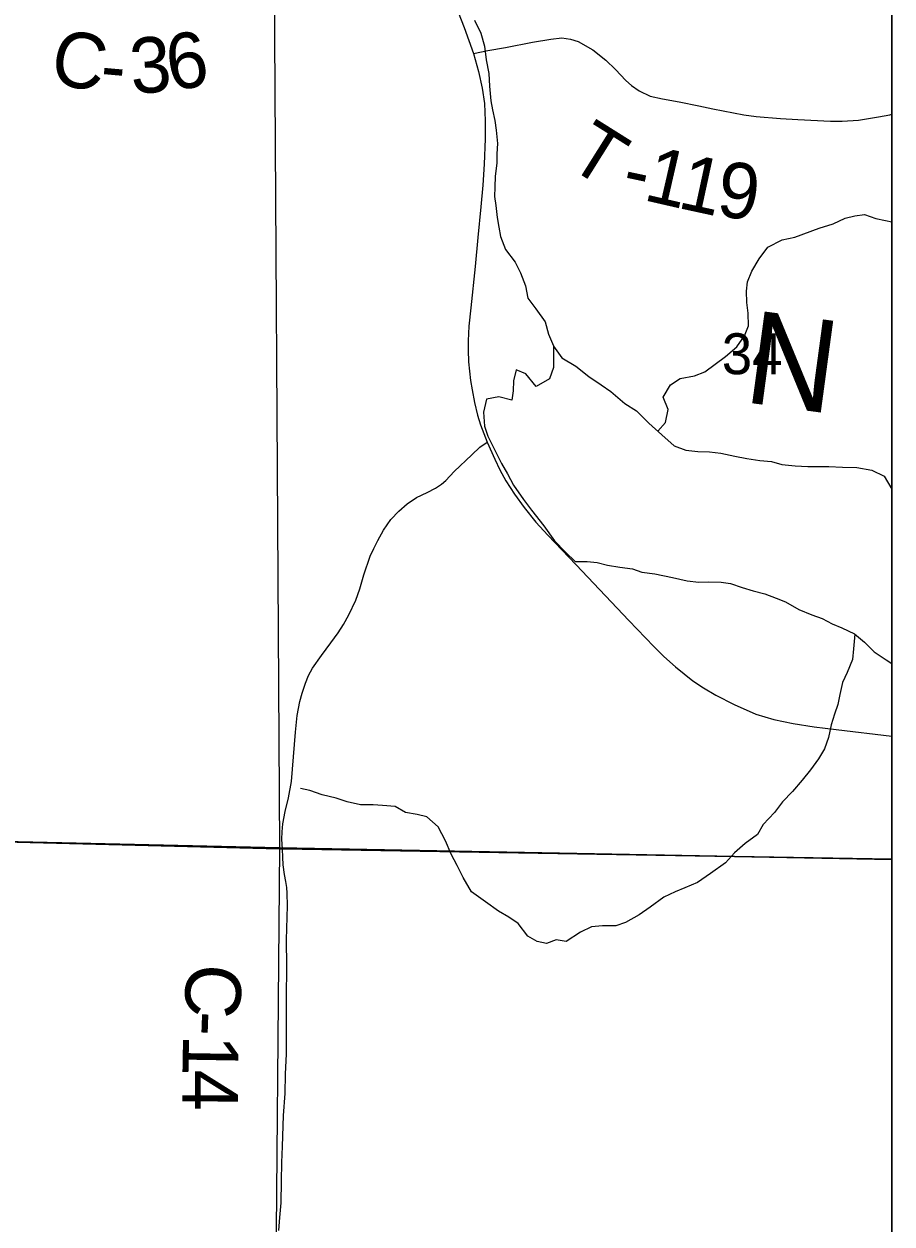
# Model space of a CAD drawing. Extents: x 0 to 34, y 0 to 22.
# Drawn here: x 7.543 to 8.431, y 15.63 to 16.857 of the extents above; entities that cross this region are included whole.
import ezdxf

# ---------------------------------------------------------------- set-up
doc = ezdxf.new("R2010")
doc.units = 0
for name, color, linetype in [('GM_X_Corporation', 7, 'Continuous'), ('GM_X_County_Road', 7, 'Continuous'), ('GM_X_County_Road_Text', 7, 'Continuous'), ('GM_X_Minor_River', 7, 'Continuous'), ('GM_X_Minor_River_Text', 7, 'Continuous'), ('GM_X_Section_Text', 7, 'Continuous'), ('GM_X_State_Route', 7, 'Continuous'), ('GM_X_Township_Road', 7, 'Continuous'), ('GM_X_Township_Road_Text', 7, 'Continuous'), ('SH_Text', 7, 'Continuous')]:
    doc.layers.add(name, color=color, linetype=linetype)

msp = doc.modelspace()

# ---------------------------------------------------------------- linework, layer by layer
at = {"layer": 'GM_X_Corporation'}
for points in [[(1.6311, 14.5734), (8.4311, 14.5734), (8.4311, 20.028)], [(4.7905, 18.3604), (4.7823, 18.128), (4.7806, 18.0273), (4.765, 16.8754), (4.756, 16.2274), (4.759, 16.0879), (4.9206, 16.0842), (4.928, 16.0841), (4.9731, 16.0831), (4.975, 16.083), (5.0347, 16.0817), (5.0373, 16.0816), (6.4668, 16.045), (6.4721, 16.0449), (6.6873, 16.0404), (6.6909, 16.0403), (6.7034, 16.04), (6.9699, 16.0345), (6.9736, 16.0344), (7.8043, 16.0135), (7.8077, 16.0135), (8.4311, 16.0029), (8.4311, 20.028)], [(3.7221, 14.5734), (8.4311, 14.5734), (8.4311, 16.0029), (7.8077, 16.0135), (7.8043, 16.0135), (6.9736, 16.0344), (6.9699, 16.0345), (6.7034, 16.04), (6.6909, 16.0403), (6.6873, 16.0404), (6.4721, 16.0449), (6.4668, 16.045), (5.0373, 16.0816)]]:
    msp.add_lwpolyline(points, dxfattribs=at)
for points in [[(7.7982, 17.0659), (7.8046, 16.0144), (6.8244, 16.0368), (6.7585, 16.0372), (6.7684, 17.0582)], [(8.4311, 16.0024), (8.4311, 17.0506), (7.7982, 17.0659), (7.8046, 16.0144)], [(6.8244, 16.0368), (7.8046, 16.0144), (7.7958, 14.9961), (6.804, 15.0104)], [(8.4311, 14.9872), (8.4311, 16.0024), (7.8046, 16.0144), (7.7958, 14.9961)]]:
    msp.add_lwpolyline(points, close=True, dxfattribs=at)
at = {"layer": 'GM_X_County_Road'}
for points in [[(7.8082, 16.005), (7.8079, 16.0129), (7.8071, 16.0233), (7.8075, 16.0309), (7.808, 16.0389), (7.8105, 16.0517), (7.8139, 16.0655), (7.8168, 16.0823), (7.821, 16.1327), (7.8229, 16.1497), (7.8256, 16.1639), (7.8279, 16.1725), (7.8313, 16.1829), (7.8345, 16.1906), (7.8383, 16.1981), (7.8478, 16.2112), (7.8572, 16.2239), (7.8647, 16.2344), (7.8703, 16.2427), (7.8757, 16.2528), (7.8827, 16.2676), (7.8868, 16.2793), (7.8911, 16.2937), (7.8975, 16.3128), (7.9011, 16.3206), (7.9051, 16.3288), (7.9112, 16.3393), (7.9187, 16.3501), (7.9269, 16.3587), (7.9351, 16.3661), (7.9449, 16.3725), (7.9557, 16.3779), (7.9643, 16.3822), (7.9704, 16.3863), (7.9748, 16.3902), (7.9835, 16.3991), (8.0013, 16.4164), (8.0096, 16.4241), (8.017, 16.4293)], [(7.804, 15.623), (7.805, 15.6363), (7.8063, 15.6515), (7.8069, 15.6735), (7.807, 15.6925), (7.8078, 15.7089), (7.8089, 15.7407), (7.8104, 15.7633), (7.811, 15.783), (7.8118, 15.8037), (7.8119, 15.8323), (7.812, 15.8607), (7.8122, 15.8935), (7.8118, 15.9205), (7.8129, 15.9551), (7.8124, 15.9679), (7.8122, 15.9738), (7.8111, 15.9801), (7.8099, 15.9872), (7.8086, 15.997), (7.8082, 16.005)]]:
    msp.add_lwpolyline(points, dxfattribs=at)
at = {"layer": 'GM_X_Minor_River'}
for points in [[(8.004, 16.8606), (8.0105, 16.8474), (8.0143, 16.8341), (8.0159, 16.8201), (8.0189, 16.8061), (8.0193, 16.7932), (8.0209, 16.7784), (8.0224, 16.769), (8.0248, 16.758), (8.0263, 16.7481), (8.0275, 16.7345), (8.0271, 16.7242), (8.0268, 16.7144), (8.0253, 16.7011), (8.025, 16.6901), (8.0246, 16.6806), (8.0258, 16.6712), (8.0273, 16.6591), (8.0289, 16.6492), (8.0308, 16.6394), (8.0357, 16.6261), (8.0456, 16.6132), (8.0513, 16.6023), (8.0563, 16.589), (8.0586, 16.5765), (8.067, 16.5656), (8.0765, 16.5523), (8.0799, 16.5398), (8.0849, 16.5277), (8.0849, 16.5057), (8.0808, 16.494), (8.0672, 16.4863), (8.0566, 16.4992), (8.0467, 16.5033), (8.0441, 16.4919), (8.0437, 16.4817), (8.0423, 16.4722), (8.029, 16.4756), (8.0165, 16.4733)], [(8.1917, 16.4404), (8.1995, 16.4493), (8.2021, 16.4625), (8.1971, 16.4754), (8.2046, 16.4879), (8.2145, 16.4944), (8.2292, 16.4971), (8.2398, 16.5013), (8.2504, 16.5089), (8.261, 16.5169), (8.2723, 16.5268), (8.2802, 16.5379), (8.2844, 16.5481), (8.2839, 16.561), (8.2828, 16.572), (8.2824, 16.5837), (8.2835, 16.5932), (8.2876, 16.6042), (8.2951, 16.6168), (8.3042, 16.6285), (8.3189, 16.6362), (8.3318, 16.6389), (8.3568, 16.648), (8.3708, 16.6526), (8.3832, 16.6584), (8.3931, 16.6607), (8.4029, 16.6619), (8.4147, 16.6581), (8.4245, 16.6559), (8.4311, 16.6544)], [(8.0849, 16.5273), (8.0936, 16.5156), (8.1077, 16.5069), (8.1209, 16.4964), (8.1338, 16.4877), (8.1437, 16.4809), (8.1578, 16.4688), (8.1699, 16.4613), (8.1824, 16.4488), (8.1957, 16.4367), (8.2082, 16.4254), (8.2204, 16.4209), (8.2325, 16.4198), (8.2446, 16.4195), (8.256, 16.418), (8.2704, 16.415), (8.2825, 16.4124), (8.2961, 16.4105), (8.3079, 16.4095), (8.3185, 16.4065), (8.3321, 16.405), (8.345, 16.4043), (8.3666, 16.4043), (8.3806, 16.4036), (8.395, 16.4033), (8.4105, 16.4007), (8.423, 16.3943), (8.4311, 16.3811)], [(8.0165, 16.4733), (8.0135, 16.46), (8.0143, 16.4456), (8.0178, 16.4354), (8.0318, 16.4074), (8.0379, 16.3968), (8.044, 16.3854), (8.0543, 16.3707), (8.0623, 16.3597), (8.0752, 16.3438), (8.0859, 16.3283), (8.0972, 16.3166), (8.1071, 16.3072), (8.1192, 16.3072), (8.1295, 16.3061), (8.1401, 16.3035), (8.1529, 16.3013), (8.1658, 16.2998), (8.1753, 16.2964), (8.1886, 16.2946), (8.2067, 16.2908), (8.2215, 16.2875), (8.2336, 16.286), (8.2435, 16.2864), (8.2564, 16.2861), (8.2658, 16.2846), (8.278, 16.2805), (8.2893, 16.2771), (8.3011, 16.2741), (8.3128, 16.2696), (8.3223, 16.2658), (8.336, 16.2583), (8.3492, 16.2527), (8.3598, 16.2489), (8.3701, 16.2436), (8.3799, 16.2395), (8.3928, 16.2331), (8.4031, 16.2248), (8.4129, 16.215), (8.4251, 16.2067), (8.4311, 16.2029)], [(8.3932, 16.2328), (8.3917, 16.2179), (8.3906, 16.2069), (8.3854, 16.1936), (8.3805, 16.1834), (8.3779, 16.1713), (8.3756, 16.161), (8.3722, 16.1511), (8.3689, 16.1401), (8.3663, 16.1272), (8.3621, 16.1155), (8.3561, 16.1056), (8.3478, 16.0942), (8.3391, 16.0836), (8.3293, 16.0721), (8.3191, 16.0615), (8.3108, 16.0505), (8.2995, 16.0383), (8.2935, 16.0281), (8.281, 16.0189), (8.2701, 16.0094), (8.261, 15.9991), (8.2455, 15.9881), (8.2323, 15.9789), (8.2194, 15.9736), (8.2092, 15.9694), (8.1979, 15.964), (8.1839, 15.9538), (8.1726, 15.9458), (8.1586, 15.9381), (8.1487, 15.9347), (8.1351, 15.9346), (8.1237, 15.9338), (8.1124, 15.9281), (8.098, 15.9186), (8.0878, 15.9204), (8.0776, 15.9166), (8.0681, 15.9185), (8.0587, 15.9241), (8.0488, 15.937), (8.0393, 15.9434), (8.0287, 15.9498), (8.0154, 15.9592), (8.001, 15.9694), (7.9926, 15.9842), (7.9865, 15.9963), (7.9804, 16.008), (7.9743, 16.0216), (7.9671, 16.036), (7.9553, 16.0462), (7.9455, 16.0485), (7.9337, 16.0507), (7.9231, 16.0567), (7.9102, 16.0578), (7.9004, 16.0585), (7.8875, 16.0585), (7.8739, 16.0615), (7.8625, 16.0652), (7.8485, 16.0686), (7.8356, 16.0731), (7.8261, 16.075)]]:
    msp.add_lwpolyline(points, dxfattribs=at)
at = {"layer": 'GM_X_State_Route'}
msp.add_lwpolyline([(7.9843, 16.8769), (7.9937, 16.8531), (8.0031, 16.8268), (8.0083, 16.8081), (8.0119, 16.7912), (8.0142, 16.7756), (8.015, 16.7578), (8.015, 16.7395), (8.014, 16.7134), (8.0127, 16.692), (8.0106, 16.67), (8.0074, 16.6386), (8.0047, 16.609), (8.0004, 16.5665), (7.9985, 16.5479), (7.9977, 16.5329), (7.9978, 16.5233), (7.9981, 16.5114), (8, 16.4923), (8.0018, 16.4828), (8.0041, 16.4697), (8.0073, 16.457), (8.0104, 16.4469), (8.017, 16.4293), (8.0248, 16.4119), (8.0299, 16.401), (8.0361, 16.3896), (8.0451, 16.3761), (8.0548, 16.3623), (8.0668, 16.3473), (8.0792, 16.334), (8.1082, 16.3038), (8.1619, 16.2468), (8.1876, 16.2202), (8.1979, 16.21), (8.2096, 16.1994), (8.2275, 16.1853), (8.2384, 16.1779), (8.2511, 16.1704), (8.2698, 16.1609), (8.2917, 16.1512), (8.3102, 16.1455), (8.3302, 16.1414), (8.3514, 16.1381), (8.3741, 16.1354), (8.4311, 16.1285)], dxfattribs=at)
at = {"layer": 'GM_X_Township_Road'}
msp.add_lwpolyline([(8.0031, 16.8268), (8.0179, 16.8297), (8.0358, 16.8328), (8.0633, 16.8382), (8.0823, 16.8414), (8.0934, 16.8426), (8.1024, 16.8413), (8.1102, 16.8388), (8.1251, 16.8305), (8.1385, 16.82), (8.1484, 16.8104), (8.1588, 16.7991), (8.1648, 16.7939), (8.1726, 16.7884), (8.1837, 16.7832), (8.1963, 16.7802), (8.2133, 16.7771), (8.2334, 16.7731), (8.248, 16.77), (8.2796, 16.7639), (8.2921, 16.7622), (8.317, 16.7601), (8.3347, 16.7591), (8.3683, 16.7574), (8.38, 16.7576), (8.3967, 16.7585), (8.4172, 16.7619), (8.4288, 16.7641), (8.4311, 16.7645)], dxfattribs=at)
at = {"layer": 'SH_Text'}
msp.add_line((8.4311, 21.373), (8.4311, 14.5734), dxfattribs=at)

# ---------------------------------------------------------------- texts
at = {"layer": 'GM_X_County_Road_Text'}
for s, rotation, p in [('C', 348.8409, (7.5679, 16.7972)), ('6', 8.6819, (7.6931, 16.7883)), ('3', 4.4346, (7.6537, 16.7851)), ('-', 354.9122, (7.6201, 16.7872)), ('C', 265.4717, (7.7108, 15.8974)), ('-', 267.9834, (7.7069, 15.8482)), ('1', 269.0142, (7.7061, 15.8237)), ('4', 269.8612, (7.7055, 15.7878))]:
    msp.add_text(s, height=0.0568, rotation=rotation, dxfattribs=at).set_placement(p)
at = {"layer": 'GM_X_Minor_River_Text'}
msp.add_text('N', height=0.0947, rotation=352.2931, dxfattribs=at).set_placement((8.2779, 16.4704))
at = {"layer": 'GM_X_Section_Text'}
msp.add_text('34', height=0.04186, rotation=0, dxfattribs=at).set_placement((8.257, 16.4987))
at = {"layer": 'GM_X_Township_Road_Text'}
for s, rotation, p in [('T', 327.8874, (8.097, 16.7126)), ('1', 347.0783, (8.1756, 16.6771)), ('1', 347.7673, (8.2104, 16.6691)), ('9', 352.8712, (8.2501, 16.6608)), ('-', 347.9518, (8.153, 16.6819))]:
    msp.add_text(s, height=0.0568, rotation=rotation, dxfattribs=at).set_placement(p)

doc.saveas('drawing.dxf')
